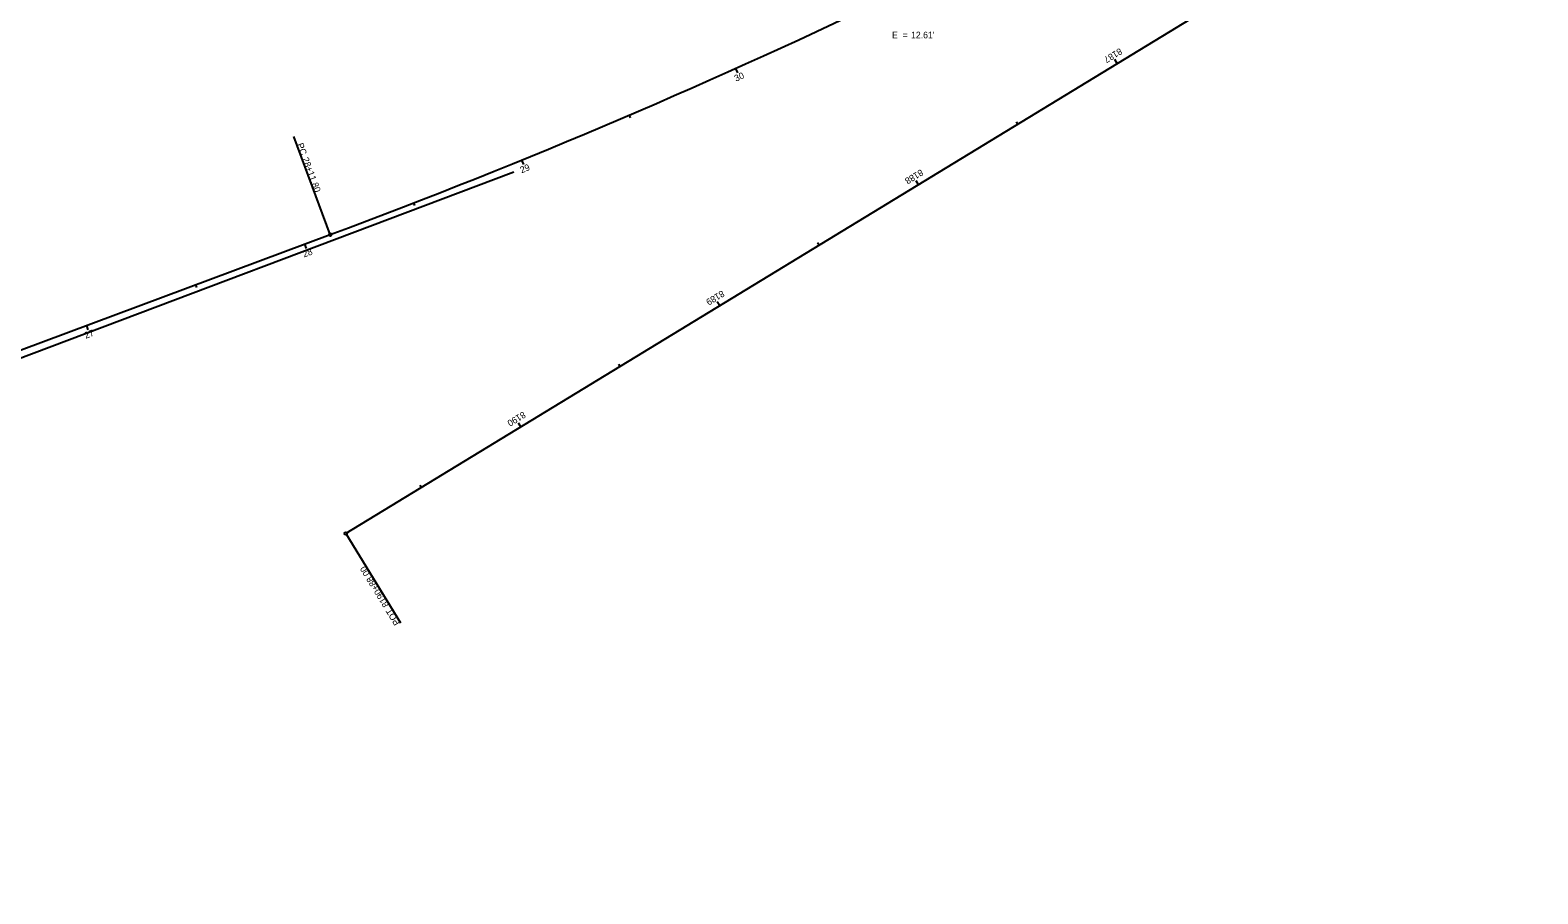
# Model space of a CAD drawing. Extents: x 2047945 to 2050534, y 355635 to 356996.
# Drawn here: x 2048592 to 2049240, y 355640 to 356011 of the extents above; entities that cross this region are included whole.
import ezdxf

# ---------------------------------------------------------------- set-up
doc = ezdxf.new("R2010")
doc.units = 0
for name, color, linetype in [('GE_X_Alignment_100_Cardinal_Points', 7, 'Continuous'), ('GE_X_Alignment_100_Curve_Data', 7, 'Continuous'), ('GE_X_Alignment_100_Stations', 7, 'Continuous'), ('RW_X_CL', 7, 'Continuous'), ('SC_Scratch1', 7, 'Continuous')]:
    doc.layers.add(name, color=color, linetype=linetype)

msp = doc.modelspace()

# ---------------------------------------------------------------- linework, layer by layer
at = {"layer": 'GE_X_Alignment_100_Cardinal_Points'}
for p, q in [((2048721.14, 355923.52), (2048705.43, 355965.69)), ((2048727.85, 355795.04), (2048751.27, 355756.62))]:
    msp.add_line(p, q, dxfattribs=at)
for centre in [(2048721.14, 355923.52), (2048727.85, 355795.04)]:
    msp.add_circle(centre, 0.6, dxfattribs=at)
at = {"layer": 'GE_X_Alignment_100_Stations'}
for p, q in [((2048895.22, 355994.94), (2048896.04, 355993.12)), ((2049059.14, 355997.01), (2049058.1, 355998.72)), ((2048849.43, 355974.85), (2048849.91, 355973.75)), ((2049016.45, 355970.98), (2049015.82, 355972.01)), ((2048803.31, 355955.56), (2048804.06, 355953.71)), ((2048973.75, 355944.96), (2048972.71, 355946.66)), ((2048756.85, 355937.09), (2048757.28, 355935.97)), ((2048710.08, 355919.4), (2048710.78, 355917.52)), ((2048931.06, 355918.93), (2048930.44, 355919.95)), ((2048663.22, 355901.95), (2048663.64, 355900.82)), ((2048888.37, 355892.9), (2048887.33, 355894.61)), ((2048616.37, 355884.5), (2048617.06, 355882.62)), ((2048845.68, 355866.88), (2048845.05, 355867.9)), ((2048802.99, 355840.85), (2048801.94, 355842.56)), ((2048760.29, 355814.82), (2048759.67, 355815.85))]:
    msp.add_line(p, q, dxfattribs=at)
at = {"layer": 'RW_X_CL'}
for p, q in [((2050510.68, 356881.9), (2048727.85, 355795.04)), ((2047960.38, 355640.2), (2048721.14, 355923.52))]:
    msp.add_line(p, q, dxfattribs=at)
msp.add_arc((2047721.35, 358608.18), 2864.79, 290.42564, 301.15897, dxfattribs=at)
at = {"layer": 'SC_Scratch1'}
msp.add_line((2048200, 355724.36), (2048800, 355950.44), dxfattribs=at)

# ---------------------------------------------------------------- texts
at = {"layer": 'GE_X_Alignment_100_Cardinal_Points'}
for s, rotation, p in [('PC', 290.42564, (2048706.75, 355962.28)), ('28+11.80', 290.42564, (2048709.03, 355956.16)), ('8190+88.00', 121.36741, (2048746.46, 355764.42)), ('POT', 121.36741, (2048751.21, 355756.63))]:
    msp.add_text(s, height=2.8, rotation=rotation, dxfattribs=at).set_placement(p)
at = {"layer": 'GE_X_Alignment_100_Curve_Data'}
for s, p in [('E  = ', (2048962.39, 356007.9)), ("12.61'", (2048970.54, 356007.9))]:
    msp.add_text(s, height=2.8, dxfattribs=at).set_placement(p)
at = {"layer": 'GE_X_Alignment_100_Stations'}
for s, rotation, p in [('8187', 211.36741, (2049060.16, 356003.84)), ('30', 24.18963, (2048895.39, 355989.21)), ('29', 22.18964, (2048803.3, 355949.84)), ('8188', 211.36741, (2048974.72, 355951.75)), ('28', 20.42564, (2048709.88, 355913.67)), ('8189', 211.36741, (2048889.32, 355899.69)), ('27', 20.42564, (2048616.11, 355878.75)), ('8190', 211.36741, (2048803.96, 355847.65))]:
    msp.add_text(s, height=2.8, rotation=rotation, dxfattribs=at).set_placement(p)

doc.saveas('drawing.dxf')
